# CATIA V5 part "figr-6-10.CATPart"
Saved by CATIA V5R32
Part number: Part1
Bounding box of the stored display mesh (mm): x -25 to 25, y -75 to 75, z 0 to 20
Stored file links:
  D:\PROJECTS\Project 2022\CATIA V5 6R 2022\Resources\Part Files\c06_catia_v5_6r2022_prt\figr-6-10.CATPart
  C:\Program Files\Dassault Systemes\B13\intel_a\reffiles\standard\MetricThinPitch.txt
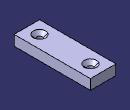
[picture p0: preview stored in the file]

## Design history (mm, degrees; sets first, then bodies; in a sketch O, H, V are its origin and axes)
Body1 (main body)
  Sketch1 on xy-plane, origin (0, 0, 0), H (1, 0, 0), V (0, 1, 0)
    line L1 (-25, 75) -> (25, 75)
    line L2 (25, 75) -> (25, -75)
    line L3 (25, -75) -> (-25, -75)
    line L4 (-25, -75) -> (-25, 75)
    axis line L5 (25, -75) -> (-25, 75)
    length L2 = 150
    length L3 = 50
    horizontal: L1 H, L3 H
    vertical: L2 V, L4 V
    midpoint: O L5
  Pad1: profile Sketch1, direction (0, 0, 1), length 20
  Sketch2 on face of Pad1, origin (-8.6664, -28.8348, 20), H (1, 0, 0), V (0, 1, 0)
    point P1 (8.6664, -21.1652)
    reference projected line E1 (-16.3336, -46.1652) -> (33.6664, -46.1652) from edge [face of Pad1 | face of Pad1]
    reference projected line E2 (-16.3336, 103.8348) -> (-16.3336, -46.1652) from edge [face of Pad1 | face of Pad1]
    distance P1 E1 = 25
    distance P1 E2 = 25
  Hole1: placed by Sketch2, at (0, -50, 20) direction (0, 0, -1), diameter 10.647, through (limit type 3), countersink depth 6, countersink angle 90
  Sketch3 on face of Pad1, origin (3.6925, 50.8892, 20), H (1, 0, 0), V (0, 1, 0)
    point P1 (-3.6925, -0.8892)
    reference projected line E1 (-28.6925, 24.1108) -> (-28.6925, -125.8892) from edge [face of Pad1 | face of Pad1]
    reference projected line E2 (21.3075, 24.1108) -> (-28.6925, 24.1108) from edge [face of Pad1 | face of Pad1]
    distance P1 E1 = 25
    distance E2 P1 = 25
  Hole2: placed by Sketch3, at (0, 50, 20) direction (0, 0, -1), diameter 10.647, through (limit type 3), countersink depth 6, countersink angle 90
